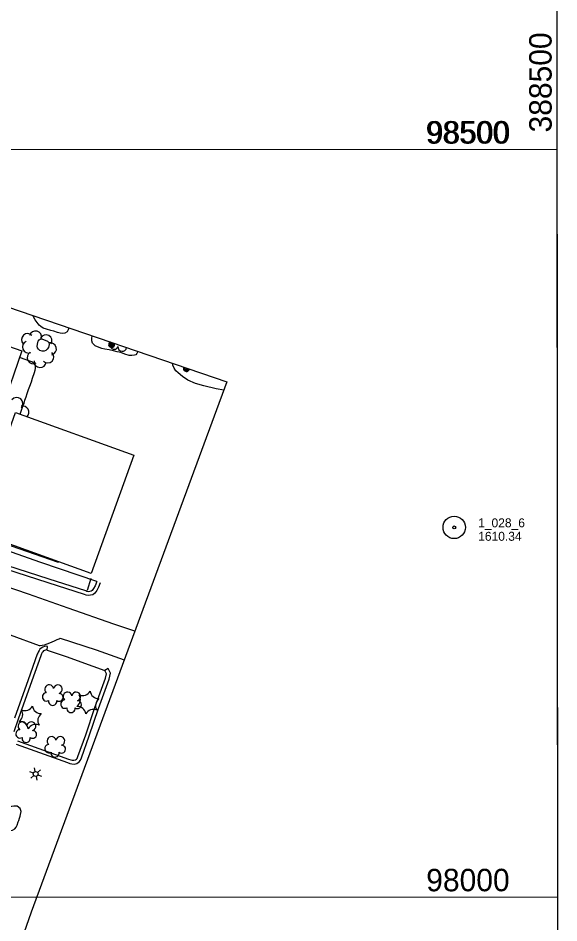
# Model space of a CAD drawing. Extents: x 189384 to 193282, y 256970 to 260388.
# Drawn here: x 191287 to 191648, y 257995 to 258600 of the extents above; entities that cross this region are included whole.
import ezdxf

# ---------------------------------------------------------------- set-up
doc = ezdxf.new("R2010")
doc.units = 0
for name, color, linetype in [('E_DWY', 7, 'Continuous'), ('E_LAND_Vegetation', 7, 'Continuous'), ('E_MAP_GridLines', 7, 'Continuous'), ('E_MAP_Limits', 7, 'Continuous'), ('E_MAP_PassPoints', 7, 'Continuous'), ('E_MISCPROP', 7, 'Continuous'), ('E_MISCPROP_HvyLine', 7, 'Continuous'), ('E_PATH_Sidewalk', 7, 'Continuous'), ('E_RDWY', 7, 'Continuous')]:
    doc.layers.add(name, color=color, linetype=linetype)

# ---------------------------------------------------------------- blocks, each defined once
blk = doc.blocks.new('PP')
at = {"layer": 'E_MAP_PassPoints'}
for radius in [7.5, 0.96]:
    blk.add_circle((0, 0), radius, dxfattribs=at)
blk = doc.blocks.new('LTP_5')
at = {"layer": 'E_MISCPROP'}
for p, q in [((-1.63, 0.07), (-4.24, 0.14)), ((-0.8, 1.43), (-2, 3.73)), ((0.9, 1.42), (2.27, 3.65)), ((-0.88, -1.42), (-2.24, -3.61)), ((0.76, -1.47), (2, -3.65)), ((1.64, -0.02), (4.16, -0.09))]:
    blk.add_line(p, q, dxfattribs=at)
blk.add_circle((0, 0), 1.64, dxfattribs=at)
blk = doc.blocks.new('TREE_3')
at = {"layer": 'E_LAND_Vegetation'}
for centre, radius, start, end in [((-1.47, 4.28), 2.78, 1.39447, 209.16747), ((-4.47, 0.2), 2.78, 78.07149, 279.08253), ((3.57, 2.42), 2.97, 278.42358, 139.65747), ((-2.01, -4.2), 2.61, 140.77963, 358.71224), ((3.46, -3.43), 2.97, 196.0744, 79.04767)]:
    blk.add_arc(centre, radius, start, end, dxfattribs=at)
blk = doc.blocks.new('PINEL_1')
at = {"layer": 'E_LAND_Vegetation'}
for centre, start, end in [((-8.14, 7.32), 275.21124, 0.97615), ((2.26, 10.71), 215.21124, 300.97615), ((-10.4, -3.39), 335.21124, 60.97615), ((10.41, 3.41), 155.21125, 240.97616), ((-2.25, -10.7), 35.21125, 120.97616), ((8.15, -7.3), 95.21125, 180.97617)]:
    blk.add_arc(centre, 5.72, start, end, dxfattribs=at)

msp = doc.modelspace()

# ---------------------------------------------------------------- linework, layer by layer
at = {"layer": 'E_DWY'}
for points in [[(191320.59, 258392.62), (191320.13, 258391.26), (191319.36, 258389.98), (191317.83, 258389.16), (191316.32, 258388.86), (191314.87, 258389.16), (191312.9, 258389.6), (191310.51, 258390.31), (191308.61, 258390.85), (191305.72, 258391.72), (191303.5, 258392.49), (191301.78, 258393.47), (191300.65, 258394.46), (191298.03, 258398.07), (191297.03, 258400.06), (191296.79, 258400.77)], [(191299.45, 258380.38), (191299.76, 258382.78), (191300.07, 258383.62), (191300.81, 258384.61), (191301.33, 258385.05), (191301.98, 258385.25), (191302.46, 258385.32), (191306.33, 258383.72)], [(191306.33, 258383.72), (191307.14, 258382.77), (191307.4, 258381.44), (191306.9, 258379.53), (191306.06, 258378.34), (191305.1, 258377.55), (191304.1, 258377.11), (191302.7, 258377.07), (191301.17, 258377.49), (191300.19, 258378.4), (191299.67, 258379.35), (191299.45, 258380.38)], [(191366.6, 258376.87), (191366.04, 258375.52), (191365.31, 258374.55), (191364.41, 258374.29), (191362.72, 258374.16), (191360.82, 258374.23), (191358.1, 258375.13), (191355.24, 258376.09), (191352.87, 258376.68), (191350.4, 258377.26), (191347.42, 258377.94), (191344.73, 258378.48), (191342.73, 258378.9), (191340.77, 258379.47), (191338.26, 258380.61), (191336.38, 258382.39), (191335.87, 258384.05), (191335.95, 258385.51), (191336.25, 258387.26)], [(191287.97, 258334.84), (191288.84, 258337.51), (191289.58, 258339.55), (191289.89, 258340.34), (191290.62, 258342.35), (191291.26, 258344.28), (191291.98, 258346.49), (191292.66, 258348.69), (191293.64, 258351.36), (191294.47, 258353.57), (191295.56, 258356.61), (191296.38, 258359), (191297.67, 258362.73), (191298.11, 258364.32), (191298.34, 258365.38), (191298.33, 258367.18), (191297.44, 258368.81), (191296.56, 258369.46), (191295.73, 258369.93), (191287.63, 258372.72)], [(191424.19, 258350.99), (191419.09, 258351.87), (191410.74, 258353.86), (191405.13, 258355.45), (191400.03, 258357.62), (191396.65, 258360.08), (191393.54, 258362.59), (191392.08, 258363.89), (191390.93, 258365.66), (191390.09, 258367.58), (191389.76, 258368.94)], [(191341.51, 258222.01), (191340.41, 258219.15), (191339.22, 258216.96), (191338.02, 258215.24), (191336.64, 258214.17), (191335.07, 258213.8), (191333.76, 258213.67), (191332.05, 258213.85), (191330.97, 258214.32), (191306.68, 258222.23), (191271.37, 258233.47), (191253.02, 258238.97), (191250.27, 258239.59), (191249.17, 258239.93), (191247.84, 258240.6), (191246.83, 258241.85), (191246.23, 258243.35), (191246.14, 258244.47), (191246.24, 258245.85), (191246.38, 258246.71)], [(191339.18, 258222.91), (191338.14, 258220.2), (191337.09, 258218.28), (191336.19, 258216.99), (191335.53, 258216.48), (191334.65, 258216.27), (191333.76, 258216.18), (191332.69, 258216.3), (191331.85, 258216.66), (191307.44, 258224.61), (191272.11, 258235.86), (191253.66, 258241.39), (191250.92, 258242.01), (191250.11, 258242.26), (191249.45, 258242.59), (191249.02, 258243.13), (191248.69, 258243.94), (191248.65, 258244.48), (191248.73, 258245.55), (191248.85, 258246.31)], [(191306, 258177.17), (191305.45, 258177.23), (191304.89, 258177.17), (191304.39, 258176.96), (191303.68, 258176.54), (191303.13, 258175.99), (191302.8, 258175.58), (191302.41, 258174.74), (191302.09, 258174.03), (191301.81, 258173.38), (191295.81, 258156.5), (191286.69, 258130.9), (191283.74, 258122.53)], [(191306, 258177.17), (191306.31, 258179.65), (191305.46, 258179.75), (191304.26, 258179.61), (191303.27, 258179.21), (191302.13, 258178.53), (191301.26, 258177.66), (191300.66, 258176.91), (191300.13, 258175.77), (191299.81, 258175.05), (191299.48, 258174.31), (191293.45, 258157.33), (191284.33, 258131.73)], [(191306, 258177.17), (191319.36, 258172.63), (191328.65, 258169.19), (191344.59, 258163.56)], [(191285.32, 258114.23), (191319.59, 258101.91), (191321.24, 258101.31), (191322.49, 258101.03), (191324.07, 258100.91), (191325.98, 258101.39), (191327.47, 258102.31), (191328.33, 258103.49), (191328.93, 258105.04), (191334.23, 258119.72), (191340.38, 258138.01), (191347.5, 258157.78), (191348.36, 258161.72), (191346.8, 258164.74), (191344.58, 258163.59)], [(191286.26, 258116.55), (191320.44, 258104.26), (191321.95, 258103.72), (191322.86, 258103.5), (191323.85, 258103.43), (191325, 258103.72), (191325.74, 258104.18), (191326.12, 258104.7), (191326.59, 258105.92), (191331.87, 258120.55), (191338.02, 258138.84), (191345.1, 258158.47), (191345.72, 258161.37), (191344.58, 258163.59)], [(191270.62, 258059.79), (191278.1, 258057.12), (191278.96, 258056.85), (191280.03, 258056.61), (191281.49, 258056.41), (191282.99, 258056.72), (191284.38, 258057.67), (191285.3, 258058.71), (191285.95, 258060.12), (191286.7, 258062.19), (191287.05, 258063.22), (191287.57, 258064.76), (191287.96, 258066.07), (191288.32, 258067.3), (191288.66, 258069.3), (191287.96, 258071.18), (191285.96, 258072.82), (191283.87, 258072.75), (191282.28, 258072.47), (191280.08, 258071.82), (191277.98, 258071.43), (191276.2, 258071.19), (191274.7, 258070.91), (191274.17, 258070.84)]]:
    msp.add_lwpolyline(points, dxfattribs=at)
at = {"layer": 'E_LAND_Vegetation'}
for centre, radius, start, end in [((191293, 258384.78), 4.03, 43.85842, 223.8431), ((191298.28, 258386.52), 4.03, 345.336, 165.32068), ((191293.63, 258379.83), 4.03, 111.82014, 291.80482), ((191305.28, 258383.89), 4.03, 331.42709, 151.41177), ((191308.28, 258378.6), 4.03, 284.07933, 104.06401), ((191350.85, 258380.94), 2.61, 132.34173, 340.3572), ((191296.72, 258372.68), 4.03, 118.48334, 298.46802), ((191306.49, 258373.25), 4.03, 226.20387, 46.18855), ((191356.28, 258379.94), 2.97, 177.71935, 349.60215), ((191301.48, 258370.14), 4.03, 175.1296, 355.11428), ((191285.63, 258341.84), 4.27, 319.7069, 139.69157), ((191289.55, 258336.1), 4.27, 316.60123, 101.37708)]:
    msp.add_arc(centre, radius, start, end, dxfattribs=at)
at = {"layer": 'E_MAP_GridLines'}
for p, q in [((191647.04, 258512.16), (191646.33, 259512.15)), ((191647.75, 257512.16), (191646.69, 259012.15)), ((189647.05, 258510.74), (191647.04, 258512.16)), ((190147.05, 258511.09), (191647.04, 258512.16)), ((190147.05, 258511.09), (191647.04, 258512.16)), ((191648.11, 257012.16), (191647.04, 258512.16)), ((189647.41, 258010.74), (191647.4, 258012.16)), ((190147.4, 258011.09), (191647.4, 258012.16))]:
    msp.add_line(p, q, dxfattribs=at)
at = {"layer": 'E_MAP_Limits'}
for points in [[(191158.05, 258448.26), (191426.21, 258356.47)], [(191426.21, 258356.47), (191295.36, 258001.93)], [(191295.36, 258001.93), (191237.77, 257837.46), (190873.21, 257154.63)]]:
    msp.add_lwpolyline(points, dxfattribs=at)
at = {"layer": 'E_MISCPROP'}
msp.add_line((191335.25, 258225.1), (191332.75, 258216.91), dxfattribs=at)
msp.add_line((191335.25, 258225.1), (191332.75, 258216.91), dxfattribs=at)
for centre, radius in [((191349.16, 258381.51), 1.01), ((191349.17, 258381.52), 0.502)]:
    msp.add_circle(centre, radius, dxfattribs=at)
for centre, radius, start, end in [((191349.16, 258381.54), 2.02, 123.39146, 18.81331), ((191349.17, 258381.55), 1.52, 107.55851, 34.64626), ((191399.16, 258365.48), 2.02, 154.62554, 347.57923), ((191399.16, 258365.48), 2.02, 154.62554, 347.57923), ((191399.16, 258365.5), 1.52, 152.98014, 349.22463), ((191399.15, 258365.46), 1.01, 146.49732, 355.70746), ((191399.16, 258365.47), 0.502, 131.95787, 10.2469)]:
    msp.add_arc(centre, radius, start, end, dxfattribs=at)
at = {"layer": 'E_MISCPROP_HvyLine'}
for points in [[(191257.11, 258388.34), (191289.2, 258377.28), (191275.98, 258338.93), (191243.89, 258349.99)], [(191284.9, 258335.94), (191363.96, 258307.6), (191335.59, 258228.44), (191254.45, 258257.52), (191262.46, 258279.88), (191264.54, 258279.13)]]:
    msp.add_lwpolyline(points, close=True, dxfattribs=at)
at = {"layer": 'E_PATH_Sidewalk'}
for points in [[(191277.17, 258249.38), (191276.96, 258248.59), (191313.49, 258235.89), (191313.61, 258236.32)], [(191339.18, 258222.91), (191301.87, 258235.66), (191274.41, 258245.34), (191271.52, 258236.04)]]:
    msp.add_lwpolyline(points, dxfattribs=at)
at = {"layer": 'E_RDWY'}
for points in [[(191364.67, 258189.73), (191350.69, 258194.53), (191320.2, 258205.24), (191293.68, 258214.61), (191260.24, 258225.93), (191206.95, 258245.11), (191166, 258261.09), (191139.89, 258270.02), (191123.72, 258276.54), (191122.11, 258292.57), (191117.18, 258342.51), (191116.85, 258347.51), (191116.97, 258348.34), (191135.27, 258400.42), (191152.49, 258450.05), (191152.52, 258450.16)], [(191281.46, 258187.27), (191300.67, 258180.26), (191301.49, 258180.21), (191302.8, 258180.35), (191304.21, 258180.67), (191306.14, 258181.31), (191307.89, 258181.95), (191309.39, 258182.61), (191311.08, 258183.38), (191312.74, 258184.13), (191314.07, 258184.73), (191314.59, 258184.94), (191314.8, 258185.02), (191338.78, 258177.3), (191357.63, 258170.66)]]:
    msp.add_lwpolyline(points, dxfattribs=at)

# ---------------------------------------------------------------- block references
at = {"layer": 'E_LAND_Vegetation'}
for name, p, rotation in [('TREE_3', (191309.89, 258147.41), 91.26356468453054), ('TREE_3', (191322.14, 258142.57), 91.26356446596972), ('PINEL_1', (191333.38, 258142.1), 91.26356426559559), ('PINEL_1', (191294.83, 258132.06), 91.26356495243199), ('TREE_3', (191292.15, 258122.69), 91.26356499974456), ('TREE_3', (191311.5, 258112.81), 91.26356465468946)]:
    msp.add_blockref(name, p, dxfattribs=dict(at, rotation=rotation))
at = {"layer": 'E_MAP_PassPoints', "rotation": 0.04070053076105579}
msp.add_blockref('PP', (191578.17, 258259.22), dxfattribs=at)
at = {"layer": 'E_MISCPROP', "rotation": -18.355095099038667}
msp.add_blockref('LTP_5', (191298.39, 258094.3), dxfattribs=at)

# ---------------------------------------------------------------- texts
at = {"layer": 'E_MAP_GridLines'}
for s, rotation, p in [('  388500  ', 90.0407, (191643.29, 258512.15)), ('  98500  ', 0.0407, (191547.93, 258515.84)), ('  98500  ', 0.0407, (191548.71, 258515.84)), ('  98000  ', 0.0407, (191548.29, 258015.84))]:
    msp.add_text(s, height=15, rotation=rotation, dxfattribs=at).set_placement(p)
at = {"layer": 'E_MAP_PassPoints'}
for s, p in [('1_028_6', (191594.17, 258259.23)), ('1610.34', (191594.18, 258250.23))]:
    msp.add_text(s, height=6, rotation=0.0407, dxfattribs=at).set_placement(p)

doc.saveas('drawing.dxf')
